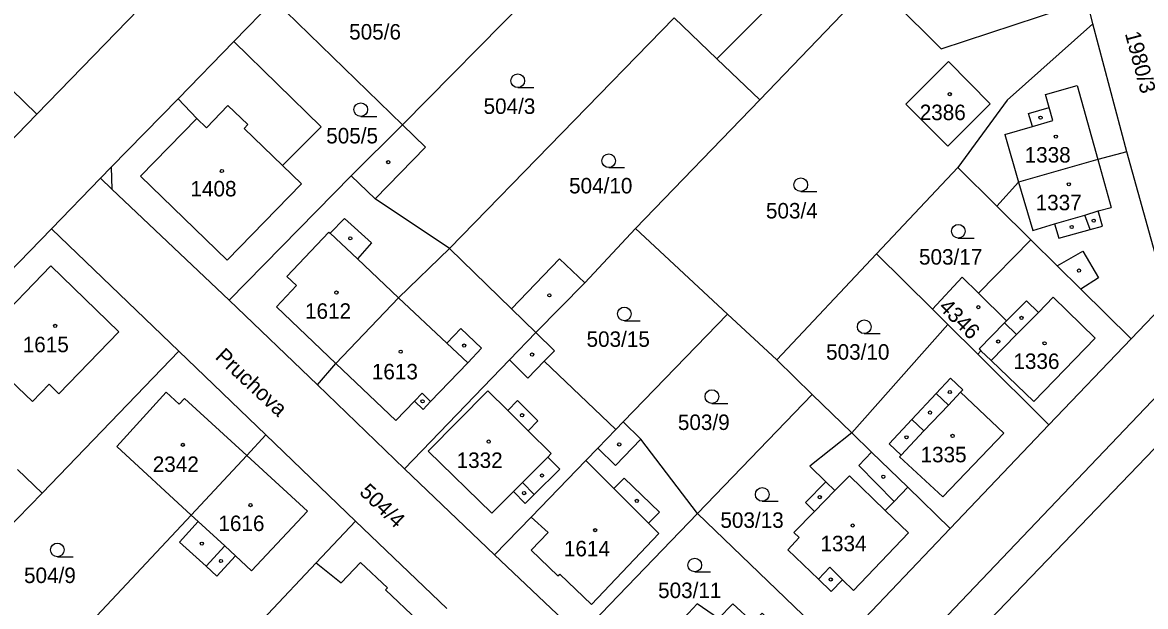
# Model space of a CAD drawing. Extents: x -679220 to -673243, y -1075091 to -1066557.
# Drawn here: x -675822.7 to -675699.3, y -1072167.4 to -1072103.3 of the extents above; entities that cross this region are included whole.
import ezdxf

# ---------------------------------------------------------------- set-up
doc = ezdxf.new("R2010")
doc.units = 0
for name, color, linetype in [('Hranice parcel', 7, 'Continuous'), ('Parcelní čísla', 7, 'Continuous'), ('Pop  PČ popisy', 7, 'Continuous'), ('Vnitřní kresba', 7, 'Continuous'), ('Značky budov', 7, 'Continuous'), ('Značky kultur', 7, 'Continuous')]:
    doc.layers.add(name, color=color, linetype=linetype)

msp = doc.modelspace()

# ---------------------------------------------------------------- linework, layer by layer
at = {"layer": 'Hranice parcel'}
for p, q in [((-675771.9, -1072062.7), (-675821.11, -1072113.32)), ((-675746.4, -1072107.27), (-675725.39, -1072086.1)), ((-675741.69, -1072111.77), (-675729.17, -1072098.71)), ((-675795.02, -1072100.79), (-675799.47, -1072105.37)), ((-675780.95, -1072114.51), (-675795.02, -1072100.79)), ((-675766.77, -1072100.12), (-675780.95, -1072114.51)), ((-675705.13, -1072103.42), (-675705.75, -1072100.88)), ((-675775.76, -1072128.09), (-675751.11, -1072102.76)), ((-675751.11, -1072102.76), (-675746.4, -1072107.27)), ((-675701.37, -1072117.47), (-675705.13, -1072103.42)), ((-675799.47, -1072105.37), (-675805.57, -1072111.65)), ((-675746.4, -1072107.27), (-675741.69, -1072111.77)), ((-675741.69, -1072111.77), (-675755.35, -1072125.89)), ((-675827.84, -1072120.31), (-675821.11, -1072113.32)), ((-675696.86, -1072133.78), (-675701.37, -1072117.47)), ((-675728.86, -1072128.67), (-675719.96, -1072119.2)), ((-675719.96, -1072119.2), (-675715.66, -1072123.44)), ((-675814.1, -1072120.37), (-675819.48, -1072125.94)), ((-675715.66, -1072123.44), (-675711.91, -1072127.14)), ((-675819.48, -1072125.94), (-675838.69, -1072145.61)), ((-675819.48, -1072125.94), (-675805.49, -1072139.38)), ((-675755.35, -1072125.89), (-675760.92, -1072131.86)), ((-675755.35, -1072125.89), (-675745.24, -1072135.29)), ((-675711.91, -1072127.14), (-675717.69, -1072133.01)), ((-675739.81, -1072140.33), (-675728.86, -1072128.67)), ((-675722.74, -1072134.75), (-675728.86, -1072128.67)), ((-675766.3, -1072137.32), (-675760.92, -1072131.86)), ((-675799.98, -1072133.77), (-675790.28, -1072143.06)), ((-675700.9, -1072138.01), (-675696.86, -1072133.78)), ((-675745.24, -1072135.29), (-675756.71, -1072147.14)), ((-675745.24, -1072135.29), (-675739.81, -1072140.33)), ((-675721.05, -1072136.42), (-675722.74, -1072134.75)), ((-675721.05, -1072136.42), (-675731.59, -1072148.33)), ((-675717.76, -1072139.69), (-675721.05, -1072136.42)), ((-675709.94, -1072147.44), (-675700.9, -1072138.01)), ((-675795.93, -1072148.57), (-675805.49, -1072139.38)), ((-675709.94, -1072147.44), (-675717.76, -1072139.69)), ((-675735.93, -1072144.11), (-675739.81, -1072140.33)), ((-675790.28, -1072143.06), (-675780.7, -1072152.28)), ((-675748.52, -1072157.21), (-675735.93, -1072144.11)), ((-675735.93, -1072144.11), (-675731.59, -1072148.33)), ((-675756.71, -1072147.14), (-675757.51, -1072147.97)), ((-675720.78, -1072158.84), (-675709.94, -1072147.44)), ((-675798.03, -1072150.82), (-675795.93, -1072148.57)), ((-675795.93, -1072148.57), (-675786.09, -1072158.02)), ((-675804.14, -1072157.36), (-675798.03, -1072150.82)), ((-675780.7, -1072152.28), (-675770.83, -1072161.73)), ((-675725.43, -1072154.31), (-675720.78, -1072158.84)), ((-675822.87, -1072177.31), (-675804.14, -1072157.36)), ((-675761.47, -1072170.59), (-675748.52, -1072157.21)), ((-675733.23, -1072171.89), (-675748.52, -1072157.21)), ((-675776.06, -1072167.63), (-675786.09, -1072158.02)), ((-675733.23, -1072171.89), (-675720.78, -1072158.84)), ((-675770.83, -1072161.73), (-675761.47, -1072170.59))]:
    msp.add_line(p, q, dxfattribs=at)
for points in [[(-675821.11, -1072113.32), (-675840.72, -1072094.24), (-675792.04, -1072044.17), (-675771.9, -1072062.7)], [(-675729.17, -1072098.71), (-675727.06, -1072100.92), (-675721.77, -1072106.17), (-675705.75, -1072100.88)], [(-675705.13, -1072103.42), (-675714.53, -1072111.81), (-675719.96, -1072119.2)], [(-675805.57, -1072111.65), (-675803.52, -1072113.8), (-675809.71, -1072120.16), (-675800.18, -1072129.36), (-675792.04, -1072120.99), (-675794.12, -1072118.98), (-675789.86, -1072114.71), (-675799.47, -1072105.37)], [(-675720.96, -1072107.56), (-675725.65, -1072112.22), (-675721.05, -1072116.84), (-675716.41, -1072112.19), (-675720.96, -1072107.56)], [(-675805.57, -1072111.65), (-675812.92, -1072119.15), (-675814.1, -1072120.37)], [(-675780.95, -1072114.51), (-675786.58, -1072120.1), (-675799.98, -1072133.77)], [(-675775.76, -1072128.09), (-675783.95, -1072122.65), (-675778.39, -1072116.97), (-675780.95, -1072114.51)], [(-675701.37, -1072117.47), (-675704.58, -1072118.31), (-675713.27, -1072120.82), (-675715.66, -1072123.44)], [(-675799.98, -1072133.77), (-675812.85, -1072121.56), (-675814.1, -1072120.37)], [(-675700.9, -1072138.01), (-675706.44, -1072132.55), (-675709.04, -1072129.98), (-675711.91, -1072127.14)], [(-675790.28, -1072143.06), (-675788.25, -1072140.71), (-675781.36, -1072133.52), (-675775.76, -1072128.09)], [(-675760.92, -1072131.86), (-675763.69, -1072129.21), (-675768.96, -1072134.71), (-675775.76, -1072128.09)], [(-675824.23, -1072141.13), (-675824.84, -1072141.77), (-675821.55, -1072144.91), (-675819.75, -1072142.98), (-675818.68, -1072144.06), (-675812.07, -1072137.25), (-675819.54, -1072129.99), (-675826.15, -1072136.81), (-675824.52, -1072138.39), (-675825.76, -1072139.67), (-675824.23, -1072141.13)], [(-675722.74, -1072134.75), (-675719.48, -1072131.25), (-675717.69, -1072133.01)], [(-675717.69, -1072133.01), (-675714.6, -1072136.05), (-675714.81, -1072136.26), (-675717.61, -1072139.12), (-675717.41, -1072139.31), (-675717.76, -1072139.69)], [(-675766.3, -1072137.32), (-675769.17, -1072140.32), (-675780.7, -1072152.28)], [(-675757.51, -1072147.97), (-675765.36, -1072140.46), (-675764.25, -1072139.31), (-675766.3, -1072137.32)], [(-675805.49, -1072139.38), (-675820.51, -1072154.95), (-675824.56, -1072159.14)], [(-675694.91, -1072140.93), (-675721.81, -1072169.15), (-675719.13, -1072171.69)], [(-675798.03, -1072150.82), (-675804.89, -1072144.56), (-675805.45, -1072145.18), (-675806.88, -1072143.88), (-675812.31, -1072149.84), (-675804.14, -1072157.36)], [(-675670.21, -1072237.22), (-675660.45, -1072222.03), (-675668.15, -1072205.56), (-675677.49, -1072184.08), (-675684.97, -1072164.88), (-675691.29, -1072147.32), (-675694.77, -1072146.33), (-675719.13, -1072171.69)], [(-675748.52, -1072157.21), (-675754.75, -1072149.03), (-675756.71, -1072147.14)], [(-675770.83, -1072161.73), (-675766.82, -1072157.59), (-675760.8, -1072151.37), (-675759.49, -1072150.02), (-675757.51, -1072147.97)], [(-675731.59, -1072148.33), (-675736.2, -1072151.98), (-675734.43, -1072153.72), (-675736.67, -1072156), (-675735.69, -1072156.96), (-675737.96, -1072159.27), (-675737.36, -1072159.84), (-675738.63, -1072161.17), (-675735.25, -1072164.42), (-675733.85, -1072165.77), (-675732.6, -1072164.48), (-675731.41, -1072165.64), (-675725.38, -1072159.32), (-675727.91, -1072156.86), (-675726.93, -1072155.86), (-675725.43, -1072154.31)], [(-675725.43, -1072154.31), (-675729.41, -1072150.45), (-675731.59, -1072148.33)], [(-675804.14, -1072157.36), (-675803.36, -1072158.08), (-675805.42, -1072160.33), (-675802.5, -1072162.99), (-675801.33, -1072164.07), (-675799.26, -1072161.84), (-675797.52, -1072163.48), (-675791.38, -1072156.93), (-675798.03, -1072150.82)], [(-675786.09, -1072158.02), (-675790.42, -1072162.6), (-675795.74, -1072168.24), (-675797.77, -1072170.38)], [(-675750.76, -1072176.62), (-675750.9, -1072176.77), (-675746.18, -1072181.27), (-675739.55, -1072174.24), (-675737.31, -1072172.03), (-675741.45, -1072168.14), (-675742.42, -1072169.17), (-675744.65, -1072167.1), (-675746.23, -1072168.71), (-675748.57, -1072167.1), (-675754.27, -1072173.27), (-675752.08, -1072175.36), (-675750.76, -1072176.62)]]:
    msp.add_lwpolyline(points, dxfattribs=at)
at = {"layer": 'Vnitřní kresba'}
for p, q in [((-675710.33, -1072111.19), (-675706.84, -1072110.18)), ((-675706.84, -1072110.18), (-675704.58, -1072118.31)), ((-675709.91, -1072112.62), (-675710.33, -1072111.19)), ((-675802.45, -1072114.83), (-675800.11, -1072112.39)), ((-675800.11, -1072112.39), (-675797.93, -1072114.48)), ((-675712.17, -1072113.28), (-675709.91, -1072112.62)), ((-675709.5, -1072114.03), (-675709.91, -1072112.62)), ((-675803.52, -1072113.8), (-675802.45, -1072114.83)), ((-675711.76, -1072114.69), (-675712.17, -1072113.28)), ((-675711.76, -1072114.69), (-675709.5, -1072114.03)), ((-675797.93, -1072114.48), (-675798.34, -1072114.91)), ((-675798.34, -1072114.91), (-675794.12, -1072118.98)), ((-675714.79, -1072115.58), (-675711.76, -1072114.69)), ((-675714.79, -1072115.58), (-675713.27, -1072120.82)), ((-675812.92, -1072119.15), (-675812.85, -1072121.56)), ((-675704.58, -1072118.31), (-675703.11, -1072123.57)), ((-675786.58, -1072120.1), (-675783.95, -1072122.65)), ((-675713.27, -1072120.82), (-675711.72, -1072126.1)), ((-675705.99, -1072124.41), (-675704.53, -1072123.96)), ((-675704.53, -1072123.96), (-675703.11, -1072123.57)), ((-675704.07, -1072125.62), (-675704.53, -1072123.96)), ((-675788.89, -1072126.4), (-675787.32, -1072124.8)), ((-675787.32, -1072124.8), (-675784.33, -1072127.47)), ((-675711.72, -1072126.1), (-675709.31, -1072125.39)), ((-675709.31, -1072125.39), (-675705.99, -1072124.41)), ((-675709.31, -1072125.39), (-675708.87, -1072126.96)), ((-675705.42, -1072126), (-675705.99, -1072124.41)), ((-675793.63, -1072131.17), (-675789.01, -1072126.3)), ((-675789.01, -1072126.3), (-675788.89, -1072126.4)), ((-675788.89, -1072126.4), (-675785.88, -1072129.24)), ((-675708.87, -1072126.96), (-675705.42, -1072126)), ((-675705.42, -1072126), (-675704.07, -1072125.62)), ((-675784.33, -1072127.47), (-675785.88, -1072129.24)), ((-675709.04, -1072129.98), (-675706.22, -1072128.4)), ((-675706.22, -1072128.4), (-675704.51, -1072131.32)), ((-675785.88, -1072129.24), (-675781.36, -1072133.52)), ((-675793.63, -1072131.17), (-675792.57, -1072132.17)), ((-675704.51, -1072131.32), (-675706.44, -1072132.55)), ((-675792.57, -1072132.17), (-675794.77, -1072134.51)), ((-675781.36, -1072133.52), (-675776.05, -1072138.5)), ((-675712.42, -1072133.82), (-675714.6, -1072136.05)), ((-675712.42, -1072133.82), (-675711.1, -1072135.11)), ((-675711.1, -1072135.11), (-675709.47, -1072133.44)), ((-675709.47, -1072133.44), (-675704.86, -1072137.95)), ((-675788.25, -1072140.71), (-675794.77, -1072134.51)), ((-675768.96, -1072134.71), (-675766.3, -1072137.32)), ((-675713.49, -1072137.55), (-675711.1, -1072135.11)), ((-675714.81, -1072136.26), (-675713.49, -1072137.55)), ((-675776.05, -1072138.5), (-675774.51, -1072136.88)), ((-675774.51, -1072136.88), (-675772.24, -1072139.04)), ((-675716.28, -1072140.39), (-675713.49, -1072137.55)), ((-675776.05, -1072138.5), (-675773.77, -1072140.64)), ((-675773.77, -1072140.64), (-675772.24, -1072139.04)), ((-675711.6, -1072144.88), (-675704.86, -1072137.95)), ((-675716.28, -1072140.39), (-675717.41, -1072139.31)), ((-675781.65, -1072146.98), (-675788.25, -1072140.71)), ((-675777.84, -1072144.9), (-675773.77, -1072140.64)), ((-675769.17, -1072140.32), (-675767.17, -1072142.32)), ((-675767.17, -1072142.32), (-675765.36, -1072140.46)), ((-675711.6, -1072144.88), (-675716.28, -1072140.39)), ((-675722.32, -1072144.02), (-675720.75, -1072142.34)), ((-675720.75, -1072142.34), (-675719.4, -1072143.61)), ((-675779.62, -1072144.85), (-675778.79, -1072143.98)), ((-675778.79, -1072143.98), (-675777.84, -1072144.9)), ((-675778.1, -1072150.36), (-675771.56, -1072143.71)), ((-675771.56, -1072143.71), (-675769.37, -1072145.88)), ((-675719.64, -1072143.86), (-675720.97, -1072145.29)), ((-675719.4, -1072143.61), (-675719.64, -1072143.86)), ((-675719.64, -1072143.86), (-675714.9, -1072148.36)), ((-675781.65, -1072146.98), (-675779.62, -1072144.85)), ((-675779.62, -1072144.85), (-675778.66, -1072145.76)), ((-675778.66, -1072145.76), (-675777.84, -1072144.9)), ((-675769.37, -1072145.88), (-675768.3, -1072144.79)), ((-675768.3, -1072144.79), (-675766.06, -1072147.02)), ((-675724.99, -1072146.88), (-675722.32, -1072144.02)), ((-675720.97, -1072145.29), (-675722.32, -1072144.02)), ((-675769.37, -1072145.88), (-675767.13, -1072148.1)), ((-675720.97, -1072145.29), (-675723.67, -1072148.11)), ((-675766.06, -1072147.02), (-675767.13, -1072148.1)), ((-675727.48, -1072149.55), (-675724.99, -1072146.88)), ((-675723.67, -1072148.11), (-675724.99, -1072146.88)), ((-675767.13, -1072148.1), (-675764.59, -1072150.62)), ((-675723.67, -1072148.11), (-675726.17, -1072150.79)), ((-675714.9, -1072148.36), (-675721.6, -1072155.38)), ((-675759.49, -1072150.02), (-675757.54, -1072151.91)), ((-675754.75, -1072149.03), (-675757.54, -1072151.91)), ((-675726.17, -1072150.79), (-675727.48, -1072149.55)), ((-675771.13, -1072157.14), (-675778.1, -1072150.36)), ((-675767.77, -1072153.79), (-675764.97, -1072151.02)), ((-675764.97, -1072151.02), (-675764.59, -1072150.62)), ((-675763.65, -1072152.31), (-675764.97, -1072151.02)), ((-675760.8, -1072151.37), (-675759.09, -1072153.08)), ((-675729.41, -1072150.45), (-675730.81, -1072151.93)), ((-675726.35, -1072150.98), (-675726.17, -1072150.79)), ((-675721.6, -1072155.38), (-675726.35, -1072150.98)), ((-675823.2, -1072152.36), (-675820.51, -1072154.95)), ((-675763.65, -1072152.31), (-675766.46, -1072155.1)), ((-675730.81, -1072151.93), (-675726.93, -1072155.86)), ((-675768.76, -1072154.77), (-675767.77, -1072153.79)), ((-675766.46, -1072155.1), (-675767.77, -1072153.79)), ((-675759.09, -1072153.08), (-675757.73, -1072154.44)), ((-675757.73, -1072154.44), (-675756.59, -1072153.3)), ((-675756.59, -1072153.3), (-675752.72, -1072157.05)), ((-675733.45, -1072154.68), (-675734.43, -1072153.72)), ((-675733.45, -1072154.68), (-675731.84, -1072153.04)), ((-675731.84, -1072153.04), (-675727.91, -1072156.86)), ((-675771.13, -1072157.14), (-675768.76, -1072154.77)), ((-675768.76, -1072154.77), (-675767.45, -1072156.09)), ((-675757.73, -1072154.44), (-675753.92, -1072158.26)), ((-675735.69, -1072156.96), (-675733.45, -1072154.68)), ((-675767.45, -1072156.09), (-675766.46, -1072155.1)), ((-675752.72, -1072157.05), (-675753.92, -1072158.26)), ((-675803.36, -1072158.08), (-675800.45, -1072160.76)), ((-675766.82, -1072157.59), (-675764.92, -1072159.27)), ((-675753.92, -1072158.26), (-675752.78, -1072159.4)), ((-675764.92, -1072159.27), (-675766.79, -1072161.22)), ((-675760.19, -1072167.19), (-675752.78, -1072159.4)), ((-675802.5, -1072162.99), (-675800.45, -1072160.76)), ((-675800.45, -1072160.76), (-675799.26, -1072161.84)), ((-675766.79, -1072161.22), (-675763.86, -1072164.04)), ((-675790.42, -1072162.6), (-675787.67, -1072164.82)), ((-675787.67, -1072164.82), (-675785.54, -1072162.57)), ((-675785.54, -1072162.57), (-675782.58, -1072165.37)), ((-675735.25, -1072164.42), (-675734.02, -1072163.1)), ((-675734.02, -1072163.1), (-675732.6, -1072164.48)), ((-675763.86, -1072164.04), (-675763.67, -1072163.85)), ((-675763.67, -1072163.85), (-675760.19, -1072167.19)), ((-675782.58, -1072165.37), (-675782.79, -1072165.59)), ((-675782.79, -1072165.59), (-675779.25, -1072168.94))]:
    msp.add_line(p, q, dxfattribs=at)
at = {"layer": 'Značky budov'}
for centre in [(-675720.83, -1072111.14), (-675710.86, -1072113.72), (-675709.18, -1072115.8), (-675782.5, -1072118.61), (-675800.77, -1072119.58), (-675707.75, -1072121.04), (-675705.02, -1072125.03), (-675707.44, -1072125.72), (-675786.67, -1072126.98), (-675706.64, -1072130.51), (-675788.19, -1072132.93), (-675764.8, -1072133.24), (-675717.7, -1072134.53), (-675819.08, -1072136.59), (-675712.95, -1072135.71), (-675774.16, -1072138.75), (-675715.51, -1072138.3), (-675710.42, -1072138.5), (-675781.13, -1072139.42), (-675766.7, -1072139.74), (-675720.82, -1072143.85), (-675778.73, -1072144.87), (-675767.8, -1072146.4), (-675723, -1072146.11), (-675725.58, -1072148.82), (-675720.52, -1072148.67), (-675805.06, -1072149.65), (-675771.47, -1072149.29), (-675757.13, -1072149.61), (-675765.61, -1072153.02), (-675728.13, -1072153.16), (-675767.58, -1072154.95), (-675797.63, -1072156.27), (-675755.2, -1072155.81), (-675735.11, -1072155.4), (-675731.49, -1072158.51), (-675759.77, -1072159.02), (-675802.97, -1072160.5), (-675800.87, -1072162.41), (-675733.9, -1072164.44)]:
    msp.add_circle(centre, 0.175, dxfattribs=at)
at = {"layer": 'Značky kultur'}
for p, q in [((-675768.27, -1072110.42), (-675766.52, -1072110.42)), ((-675785.52, -1072113.59), (-675783.77, -1072113.59)), ((-675758.29, -1072119.21), (-675756.54, -1072119.21)), ((-675737.19, -1072121.83), (-675735.44, -1072121.83)), ((-675719.89, -1072126.94), (-675718.14, -1072126.94)), ((-675756.57, -1072136.02), (-675754.82, -1072136.02)), ((-675730.22, -1072137.43), (-675728.47, -1072137.43)), ((-675746.95, -1072145.1), (-675745.2, -1072145.1)), ((-675741.43, -1072155.85), (-675739.68, -1072155.85)), ((-675818.84, -1072161.94), (-675817.09, -1072161.94)), ((-675748.84, -1072163.6), (-675747.09, -1072163.6))]:
    msp.add_line(p, q, dxfattribs=at)
for centre in [(-675768.27, -1072109.67), (-675785.52, -1072112.84), (-675758.29, -1072118.46), (-675737.19, -1072121.08), (-675719.89, -1072126.19), (-675756.57, -1072135.27), (-675730.22, -1072136.68), (-675746.95, -1072144.35), (-675741.43, -1072155.1), (-675818.84, -1072161.19), (-675748.84, -1072162.85)]:
    msp.add_circle(centre, 0.75, dxfattribs=at)

# ---------------------------------------------------------------- texts
at = {"layer": 'Parcelní čísla'}
for s, p in [('505/6', (-675786.79, -1072105.14)), ('504/3', (-675772.03, -1072113.31)), ('2386', (-675724.13, -1072113.99)), ('505/5', (-675789.31, -1072116.55)), ('1338', (-675712.61, -1072118.65)), ('504/10', (-675762.64, -1072122.04)), ('1408', (-675804.22, -1072122.37)), ('503/4', (-675741.02, -1072124.79)), ('1337', (-675711.4, -1072123.89)), ('503/17', (-675724.21, -1072129.86)), ('1612', (-675791.64, -1072135.81)), ('1615', (-675822.64, -1072139.48)), ('503/15', (-675760.72, -1072138.89)), ('503/10', (-675734.41, -1072140.3)), ('1336', (-675713.84, -1072141.32)), ('1613', (-675784.3, -1072142.46)), ('503/9', (-675750.69, -1072148.02)), ('1335', (-675724.04, -1072151.57)), ('2342', (-675808.36, -1072152.63)), ('1332', (-675774.99, -1072152.19)), ('1616', (-675801.15, -1072159.12)), ('503/13', (-675746.02, -1072158.77)), ('1334', (-675735.03, -1072161.34)), ('1614', (-675763.21, -1072161.9)), ('504/9', (-675822.5, -1072164.83)), ('503/11', (-675752.86, -1072166.48))]:
    msp.add_text(s, height=1.7, dxfattribs=at).set_placement(p)
for s, rotation, p in [('1980/3', 285, (-675701.61, -1072104.48)), ('4346', 315, (-675722.13, -1072134.63)), ('504/4', 316, (-675785.77, -1072154.96))]:
    msp.add_text(s, height=1.7, rotation=rotation, dxfattribs=at).set_placement(p)
at = {"layer": 'Pop  PČ popisy'}
msp.add_text('Pruchova', height=1.7, rotation=317, dxfattribs=at).set_placement((-675801.6, -1072140.11))

doc.saveas('drawing.dxf')
